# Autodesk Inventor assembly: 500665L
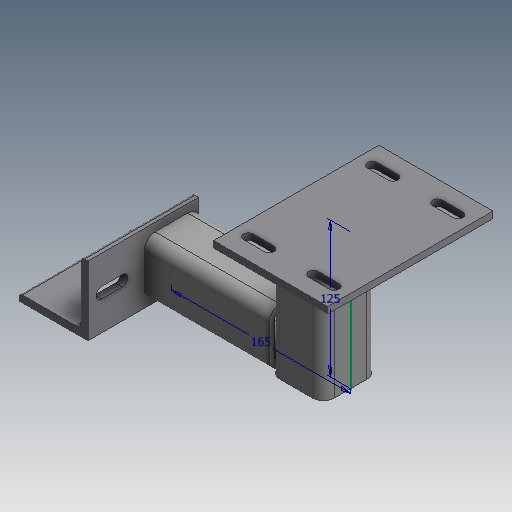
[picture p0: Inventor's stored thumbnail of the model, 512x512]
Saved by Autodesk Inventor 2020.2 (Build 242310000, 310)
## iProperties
_SolveAssemblyDoc: Frame Generator Solve Assembly
_Version: 15.0.0
Shininess: 0.0
Length Units: 11269
Angle Units: 11279
Time Units: 11290
Mass Units: 11283
Length Display Precision: 3
Angle Display Precision: 2
Compacted: True
Created: 2000-02
Part Number: 500665L
Document SubType Name: Assembly
Description: WMT-CP,TU,XX,ADJUSTABLE RAIL MOUNT,HOPPER PAN
Designer: sspink
Mass: 1546.91 g
Surface Area: 1487.37 cm^2
Volume: 372.477 cm^3
Density: 4.15302 g/cm^3
Density: 0.0
Volumn: 0.0
Area: 0.0
PropertySet Name: Model Information
Control State: 0
Checked Out: False
Master: False
Dimensions: 137x152,6x283,5 mm
Mass: 1,547 kg
DocNumber: 500665L.iam
Folder: 01 - Themengebiete\Simplification\01 - Packaging machine\
VDS_Category: 3D Komponenten
Author: sspink
Revision Number: -
Title: 500665L
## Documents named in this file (5)
- D:\07 - DEMODATEN\OTX 2019 - Dataset - UPDATE - Dez2019\Designs\07-Packing machine\500665L.iam
- D:\07 - DEMODATEN\OTX 2019 - Dataset - UPDATE - Dez2019\Designs\07-Packing machine\Parts\ADSK-011642.ipt
- D:\07 - DEMODATEN\OTX 2019 - Dataset - UPDATE - Dez2019\Designs\07-Packing machine\Parts\ADSK-011643.ipt
- D:\07 - DEMODATEN\OTX 2019 - Dataset - UPDATE - Dez2019\Designs\07-Packing machine\Parts\ADSK-014426.ipt
- D:\07 - DEMODATEN\OTX 2019 - Dataset - UPDATE - Dez2019\Designs\07-Packing machine\500665L\Frame\ADSK-014427.iam
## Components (4 placed, 4 different names)
1. ADSK-014426:1
2. ADSK-011642:1 — Passend:6, Fluchtend:7, Fluchtend:10
3. ADSK-014427:1 [sub-assembly] — Passend:6, Fluchtend:7, Fluchtend:10, Passend:8, Fluchtend:8, Fluchtend:9
4. ADSK-011643:2 — Passend:8, Fluchtend:8, Fluchtend:9
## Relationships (6: Flush 4, Mate 2)
- Passend:6 [Mate]: ADSK-011642:1 ↔ ADSK-014427:1
- Fluchtend:7 [Flush]: ADSK-011642:1 ↔ ADSK-014427:1
- Fluchtend:10 [Flush]: ADSK-011642:1 ↔ ADSK-014427:1
- Passend:8 [Mate]: ADSK-014427:1 ↔ ADSK-011643:2
- Fluchtend:8 [Flush]: ADSK-014427:1 ↔ ADSK-011643:2
- Fluchtend:9 [Flush]: ADSK-014427:1 ↔ ADSK-011643:2
